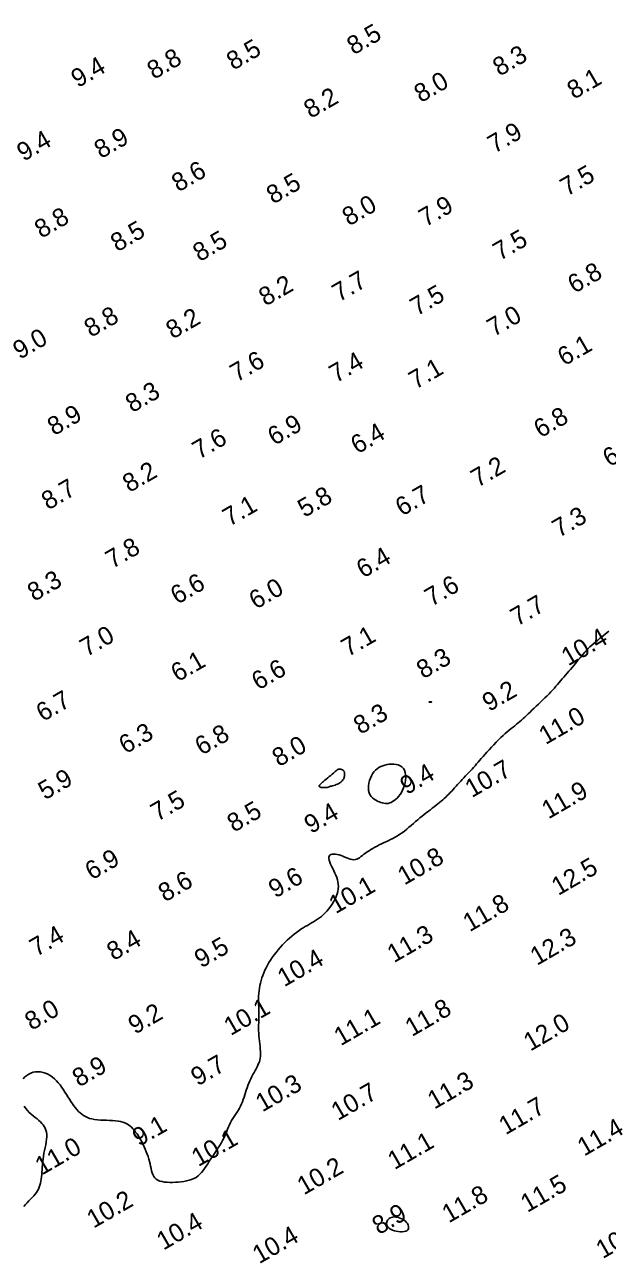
# Model space of a CAD drawing. Extents: x 3024098 to 3056816, y 418252 to 509144.
# Drawn here: x 3034142.8 to 3034302.4, y 418682.1 to 419020.7 of the extents above; entities that cross this region are included whole.
import ezdxf

# ---------------------------------------------------------------- set-up
doc = ezdxf.new("R2010")
doc.units = 0
doc.layers.add('V-CHAN-CONT-EL10', color=7, linetype='Continuous')
doc.layers.add('V-TOPO-SOUN-0911', color=7, linetype='Continuous')

msp = doc.modelspace()

# ---------------------------------------------------------------- linework, layer by layer
at = {"layer": 'V-CHAN-CONT-EL10'}
for points in [[(3034142.44, 418731.86), (3034142.89, 418732.36), (3034143.39, 418732.79), (3034143.95, 418733.15), (3034144.55, 418733.43), (3034145.18, 418733.63), (3034145.83, 418733.75), (3034146.5, 418733.78), (3034147.18, 418733.72), (3034147.85, 418733.59), (3034148.52, 418733.39), (3034149.18, 418733.11), (3034149.81, 418732.76), (3034150.42, 418732.34), (3034150.99, 418731.87), (3034151.53, 418731.33), (3034152.04, 418730.76), (3034152.52, 418730.15), (3034152.98, 418729.51), (3034153.43, 418728.85), (3034153.85, 418728.19), (3034154.27, 418727.53), (3034154.68, 418726.87), (3034155.08, 418726.23), (3034155.49, 418725.61), (3034155.89, 418725.02), (3034156.29, 418724.45), (3034156.71, 418723.9), (3034157.12, 418723.4), (3034157.55, 418722.93), (3034158, 418722.51), (3034158.46, 418722.12), (3034158.95, 418721.78), (3034159.46, 418721.48), (3034160.02, 418721.23), (3034160.62, 418721.01), (3034161.27, 418720.84), (3034161.98, 418720.71), (3034162.75, 418720.61), (3034163.56, 418720.55), (3034164.4, 418720.51), (3034165.25, 418720.48), (3034166.1, 418720.44), (3034166.93, 418720.4), (3034167.72, 418720.35), (3034168.45, 418720.26), (3034169.12, 418720.13), (3034169.72, 418719.97), (3034170.27, 418719.77), (3034170.77, 418719.53), (3034171.23, 418719.25), (3034171.66, 418718.93), (3034172.07, 418718.57), (3034172.46, 418718.17), (3034172.85, 418717.73), (3034173.23, 418717.26), (3034173.61, 418716.75), (3034173.97, 418716.21), (3034174.32, 418715.65), (3034174.66, 418715.06), (3034174.99, 418714.45), (3034175.3, 418713.82), (3034175.6, 418713.18), (3034175.88, 418712.53), (3034176.14, 418711.87), (3034176.39, 418711.2), (3034176.62, 418710.53), (3034176.82, 418709.86), (3034177.01, 418709.2), (3034177.17, 418708.54), (3034177.32, 418707.9), (3034177.46, 418707.28), (3034177.6, 418706.67), (3034177.77, 418706.11), (3034177.96, 418705.59), (3034178.2, 418705.11), (3034178.5, 418704.69), (3034178.88, 418704.34), (3034179.34, 418704.05), (3034179.87, 418703.83), (3034180.48, 418703.67), (3034181.13, 418703.57), (3034181.83, 418703.5), (3034182.57, 418703.48), (3034183.33, 418703.48), (3034184.11, 418703.51), (3034184.89, 418703.56), (3034185.66, 418703.63), (3034186.43, 418703.73), (3034187.17, 418703.86), (3034187.89, 418704.03), (3034188.57, 418704.25), (3034189.21, 418704.52), (3034189.8, 418704.85), (3034190.34, 418705.23), (3034190.83, 418705.68), (3034191.29, 418706.17), (3034191.72, 418706.72), (3034192.13, 418707.3), (3034192.54, 418707.92), (3034192.96, 418708.57), (3034193.39, 418709.24), (3034193.85, 418709.93), (3034194.33, 418710.64), (3034194.82, 418711.36), (3034195.3, 418712.08), (3034195.77, 418712.8), (3034196.22, 418713.52), (3034196.64, 418714.22), (3034197.02, 418714.91), (3034197.36, 418715.58), (3034197.65, 418716.23), (3034197.91, 418716.86), (3034198.16, 418717.48), (3034198.4, 418718.08), (3034198.65, 418718.67), (3034198.9, 418719.26), (3034199.19, 418719.83), (3034199.51, 418720.39), (3034199.85, 418720.95), (3034200.22, 418721.51), (3034200.59, 418722.07), (3034200.96, 418722.63), (3034201.32, 418723.2), (3034201.67, 418723.77), (3034201.98, 418724.36), (3034202.25, 418724.96), (3034202.5, 418725.58), (3034202.72, 418726.2), (3034202.93, 418726.83), (3034203.12, 418727.47), (3034203.32, 418728.11), (3034203.52, 418728.75), (3034203.74, 418729.39), (3034203.98, 418730.03), (3034204.24, 418730.66), (3034204.51, 418731.28), (3034204.79, 418731.88), (3034205.07, 418732.47), (3034205.36, 418733.04), (3034205.65, 418733.59), (3034205.93, 418734.11), (3034206.21, 418734.61), (3034206.47, 418735.09), (3034206.71, 418735.55), (3034206.92, 418736.02), (3034207.11, 418736.49), (3034207.26, 418736.99), (3034207.37, 418737.51), (3034207.44, 418738.07), (3034207.45, 418738.68), (3034207.43, 418739.32), (3034207.37, 418740), (3034207.3, 418740.71), (3034207.21, 418741.43), (3034207.12, 418742.17), (3034207.03, 418742.91), (3034206.97, 418743.65), (3034206.93, 418744.38), (3034206.91, 418745.11), (3034206.91, 418745.83), (3034206.92, 418746.54), (3034206.94, 418747.25), (3034206.95, 418747.97), (3034206.97, 418748.68), (3034206.97, 418749.4), (3034206.97, 418750.13), (3034206.95, 418750.85), (3034206.93, 418751.59), (3034206.91, 418752.32), (3034206.9, 418753.05), (3034206.9, 418753.78), (3034206.92, 418754.51), (3034206.96, 418755.23), (3034207.02, 418755.95), (3034207.12, 418756.66), (3034207.24, 418757.37), (3034207.39, 418758.07), (3034207.57, 418758.77), (3034207.78, 418759.47), (3034208.03, 418760.17), (3034208.3, 418760.87), (3034208.61, 418761.57), (3034208.96, 418762.27), (3034209.33, 418762.98), (3034209.74, 418763.68), (3034210.18, 418764.38), (3034210.65, 418765.08), (3034211.15, 418765.78), (3034211.69, 418766.47), (3034212.25, 418767.17), (3034212.84, 418767.85), (3034213.45, 418768.53), (3034214.08, 418769.18), (3034214.71, 418769.81), (3034215.36, 418770.41), (3034216, 418770.97), (3034216.64, 418771.5), (3034217.27, 418771.97), (3034217.89, 418772.41), (3034218.51, 418772.82), (3034219.11, 418773.2), (3034219.7, 418773.55), (3034220.29, 418773.89), (3034220.86, 418774.22), (3034221.43, 418774.55), (3034221.98, 418774.88), (3034222.53, 418775.22), (3034223.07, 418775.57), (3034223.6, 418775.95), (3034224.12, 418776.36), (3034224.63, 418776.8), (3034225.14, 418777.28), (3034225.64, 418777.82), (3034226.13, 418778.4), (3034226.6, 418779.03), (3034227.05, 418779.69), (3034227.46, 418780.38), (3034227.84, 418781.09), (3034228.16, 418781.79), (3034228.42, 418782.5), (3034228.6, 418783.19), (3034228.71, 418783.86), (3034228.75, 418784.52), (3034228.73, 418785.15), (3034228.64, 418785.77), (3034228.5, 418786.39), (3034228.31, 418787), (3034228.08, 418787.62), (3034227.81, 418788.23), (3034227.51, 418788.86), (3034227.2, 418789.48), (3034226.9, 418790.09), (3034226.62, 418790.67), (3034226.38, 418791.22), (3034226.21, 418791.73), (3034226.1, 418792.18), (3034226.1, 418792.56), (3034226.2, 418792.88), (3034226.4, 418793.12), (3034226.69, 418793.29), (3034227.05, 418793.39), (3034227.47, 418793.43), (3034227.94, 418793.41), (3034228.44, 418793.34), (3034228.95, 418793.21), (3034229.48, 418793.03), (3034230, 418792.82), (3034230.52, 418792.59), (3034231.04, 418792.37), (3034231.54, 418792.17), (3034232.03, 418792), (3034232.5, 418791.89), (3034232.95, 418791.84), (3034233.38, 418791.89), (3034233.78, 418792), (3034234.17, 418792.19), (3034234.56, 418792.42), (3034234.95, 418792.71), (3034235.35, 418793.02), (3034235.76, 418793.35), (3034236.19, 418793.68), (3034236.66, 418794.02), (3034237.15, 418794.35), (3034237.66, 418794.67), (3034238.2, 418794.99), (3034238.76, 418795.31), (3034239.34, 418795.62), (3034239.93, 418795.92), (3034240.53, 418796.22), (3034241.15, 418796.51), (3034241.77, 418796.8), (3034242.4, 418797.09), (3034243.04, 418797.4), (3034243.68, 418797.72), (3034244.31, 418798.06), (3034244.95, 418798.43), (3034245.59, 418798.83), (3034246.22, 418799.27), (3034246.85, 418799.74), (3034247.47, 418800.24), (3034248.09, 418800.75), (3034248.7, 418801.27), (3034249.31, 418801.8), (3034249.92, 418802.33), (3034250.51, 418802.84), (3034251.11, 418803.33), (3034251.7, 418803.81), (3034252.28, 418804.28), (3034252.85, 418804.73), (3034253.41, 418805.16), (3034253.95, 418805.58), (3034254.49, 418805.99), (3034255, 418806.39), (3034255.5, 418806.78), (3034255.98, 418807.16), (3034256.45, 418807.53), (3034256.9, 418807.91), (3034257.34, 418808.28), (3034257.77, 418808.66), (3034258.19, 418809.04), (3034258.6, 418809.43), (3034259, 418809.84), (3034259.4, 418810.26), (3034259.8, 418810.68), (3034260.19, 418811.12), (3034260.59, 418811.56), (3034261, 418812.01), (3034261.41, 418812.47), (3034261.83, 418812.93), (3034262.26, 418813.4), (3034262.71, 418813.88), (3034263.15, 418814.35), (3034263.6, 418814.83), (3034264.05, 418815.3), (3034264.5, 418815.77), (3034264.94, 418816.24), (3034265.37, 418816.71), (3034265.78, 418817.17), (3034266.19, 418817.63), (3034266.6, 418818.1), (3034267.01, 418818.58), (3034267.44, 418819.08), (3034267.89, 418819.6), (3034268.38, 418820.15), (3034268.9, 418820.74), (3034269.46, 418821.36), (3034270.05, 418822.02), (3034270.67, 418822.69), (3034271.31, 418823.37), (3034271.96, 418824.05), (3034272.61, 418824.7), (3034273.25, 418825.33), (3034273.87, 418825.92), (3034274.46, 418826.45), (3034275.03, 418826.94), (3034275.58, 418827.4), (3034276.1, 418827.82), (3034276.61, 418828.22), (3034277.1, 418828.6), (3034277.57, 418828.98), (3034278.03, 418829.35), (3034278.48, 418829.74), (3034278.92, 418830.13), (3034279.37, 418830.54), (3034279.82, 418830.96), (3034280.28, 418831.4), (3034280.76, 418831.86), (3034281.26, 418832.34), (3034281.79, 418832.85), (3034282.35, 418833.38), (3034282.93, 418833.93), (3034283.54, 418834.49), (3034284.15, 418835.07), (3034284.75, 418835.65), (3034285.35, 418836.23), (3034285.93, 418836.79), (3034286.47, 418837.35), (3034286.98, 418837.88), (3034287.46, 418838.4), (3034287.92, 418838.9), (3034288.36, 418839.4), (3034288.78, 418839.9), (3034289.2, 418840.39), (3034289.62, 418840.88), (3034290.05, 418841.39), (3034290.49, 418841.9), (3034290.94, 418842.42), (3034291.4, 418842.96), (3034291.86, 418843.49), (3034292.33, 418844.03), (3034292.79, 418844.57), (3034293.24, 418845.1), (3034293.69, 418845.64), (3034294.12, 418846.16), (3034294.55, 418846.69), (3034294.97, 418847.2), (3034295.4, 418847.71), (3034295.83, 418848.22), (3034296.27, 418848.72), (3034296.72, 418849.21), (3034297.19, 418849.7), (3034297.68, 418850.18), (3034298.19, 418850.66), (3034298.72, 418851.12), (3034299.25, 418851.58), (3034299.79, 418852.03), (3034300.32, 418852.47), (3034300.85, 418852.89), (3034301.37, 418853.3), (3034301.87, 418853.7), (3034302.36, 418854.09), (3034302.83, 418854.46)], [(3034142.61, 418696.84), (3034143.06, 418697.38), (3034143.52, 418697.89), (3034143.98, 418698.38), (3034144.44, 418698.85), (3034144.88, 418699.32), (3034145.3, 418699.77), (3034145.69, 418700.23), (3034146.04, 418700.69), (3034146.35, 418701.16), (3034146.6, 418701.65), (3034146.82, 418702.15), (3034147, 418702.67), (3034147.15, 418703.21), (3034147.27, 418703.77), (3034147.36, 418704.36), (3034147.44, 418704.97), (3034147.5, 418705.6), (3034147.56, 418706.26), (3034147.6, 418706.94), (3034147.66, 418707.64), (3034147.71, 418708.37), (3034147.79, 418709.11), (3034147.88, 418709.87), (3034147.99, 418710.65), (3034148.12, 418711.43), (3034148.28, 418712.23), (3034148.44, 418713.02), (3034148.58, 418713.8), (3034148.71, 418714.55), (3034148.81, 418715.29), (3034148.87, 418715.98), (3034148.86, 418716.63), (3034148.79, 418717.22), (3034148.66, 418717.77), (3034148.46, 418718.28), (3034148.21, 418718.75), (3034147.9, 418719.2), (3034147.55, 418719.63), (3034147.14, 418720.05), (3034146.69, 418720.46), (3034146.21, 418720.87), (3034145.7, 418721.29), (3034145.17, 418721.72), (3034144.63, 418722.18), (3034144.1, 418722.66), (3034143.6, 418723.18), (3034143.12, 418723.73), (3034142.68, 418724.34)]]:
    msp.add_lwpolyline(points, dxfattribs=at)
for points in [[(3034253.66, 418835.03), (3034253.65, 418835.04), (3034253.65, 418835.05), (3034253.65, 418835.06), (3034253.66, 418835.08), (3034253.66, 418835.09), (3034253.67, 418835.1), (3034253.67, 418835.11), (3034253.68, 418835.12), (3034253.68, 418835.13), (3034253.69, 418835.14), (3034253.69, 418835.15), (3034253.7, 418835.15), (3034253.7, 418835.15), (3034253.71, 418835.16), (3034253.71, 418835.16), (3034253.72, 418835.16), (3034253.73, 418835.17), (3034253.74, 418835.17), (3034253.76, 418835.17), (3034253.78, 418835.17), (3034253.81, 418835.17), (3034253.84, 418835.16), (3034253.89, 418835.16), (3034253.95, 418835.16), (3034254.01, 418835.15), (3034254.08, 418835.14), (3034254.14, 418835.13), (3034254.19, 418835.12), (3034254.24, 418835.11), (3034254.27, 418835.1), (3034254.28, 418835.09), (3034254.27, 418835.08), (3034254.24, 418835.07), (3034254.19, 418835.05), (3034254.13, 418835.04), (3034254.07, 418835.03), (3034254, 418835.02), (3034253.93, 418835.02), (3034253.87, 418835.01), (3034253.82, 418835), (3034253.78, 418835), (3034253.74, 418835), (3034253.72, 418835), (3034253.69, 418835), (3034253.68, 418835), (3034253.67, 418835.01), (3034253.66, 418835.02)], [(3034237.05, 418810.83), (3034237, 418811.47), (3034237.03, 418812.15), (3034237.13, 418812.84), (3034237.3, 418813.54), (3034237.53, 418814.21), (3034237.81, 418814.85), (3034238.14, 418815.43), (3034238.51, 418815.95), (3034238.92, 418816.4), (3034239.36, 418816.79), (3034239.84, 418817.12), (3034240.36, 418817.39), (3034240.9, 418817.62), (3034241.48, 418817.79), (3034242.08, 418817.93), (3034242.71, 418818.02), (3034243.35, 418818.07), (3034243.98, 418818.05), (3034244.6, 418817.98), (3034245.18, 418817.84), (3034245.71, 418817.61), (3034246.18, 418817.3), (3034246.56, 418816.9), (3034246.85, 418816.39), (3034247.05, 418815.8), (3034247.16, 418815.14), (3034247.2, 418814.44), (3034247.15, 418813.71), (3034247.04, 418812.97), (3034246.87, 418812.24), (3034246.64, 418811.54), (3034246.35, 418810.89), (3034246.02, 418810.28), (3034245.66, 418809.73), (3034245.27, 418809.23), (3034244.86, 418808.78), (3034244.44, 418808.39), (3034244.02, 418808.06), (3034243.61, 418807.79), (3034243.21, 418807.58), (3034242.82, 418807.42), (3034242.43, 418807.32), (3034242.05, 418807.28), (3034241.65, 418807.28), (3034241.25, 418807.33), (3034240.83, 418807.42), (3034240.39, 418807.55), (3034239.93, 418807.71), (3034239.45, 418807.92), (3034238.98, 418808.17), (3034238.52, 418808.47), (3034238.1, 418808.83), (3034237.73, 418809.23), (3034237.42, 418809.7), (3034237.19, 418810.23)], [(3034223.62, 418812.3), (3034223.64, 418812.34), (3034223.68, 418812.39), (3034223.75, 418812.47), (3034223.84, 418812.57), (3034223.98, 418812.7), (3034224.16, 418812.87), (3034224.4, 418813.08), (3034224.71, 418813.34), (3034225.06, 418813.64), (3034225.44, 418813.97), (3034225.85, 418814.31), (3034226.26, 418814.65), (3034226.66, 418814.99), (3034227.04, 418815.31), (3034227.38, 418815.6), (3034227.67, 418815.86), (3034227.91, 418816.07), (3034228.11, 418816.25), (3034228.29, 418816.39), (3034228.44, 418816.51), (3034228.57, 418816.59), (3034228.71, 418816.65), (3034228.84, 418816.69), (3034228.98, 418816.71), (3034229.12, 418816.71), (3034229.27, 418816.7), (3034229.42, 418816.67), (3034229.57, 418816.63), (3034229.71, 418816.59), (3034229.83, 418816.53), (3034229.95, 418816.47), (3034230.04, 418816.41), (3034230.12, 418816.34), (3034230.19, 418816.27), (3034230.25, 418816.19), (3034230.29, 418816.11), (3034230.33, 418816.02), (3034230.37, 418815.92), (3034230.39, 418815.82), (3034230.42, 418815.7), (3034230.44, 418815.58), (3034230.45, 418815.45), (3034230.46, 418815.3), (3034230.45, 418815.15), (3034230.44, 418814.98), (3034230.41, 418814.8), (3034230.36, 418814.6), (3034230.3, 418814.39), (3034230.22, 418814.17), (3034230.12, 418813.95), (3034229.99, 418813.73), (3034229.83, 418813.5), (3034229.64, 418813.29), (3034229.42, 418813.09), (3034229.15, 418812.9), (3034228.85, 418812.73), (3034228.53, 418812.58), (3034228.18, 418812.45), (3034227.84, 418812.34), (3034227.5, 418812.24), (3034227.17, 418812.15), (3034226.88, 418812.07), (3034226.64, 418812), (3034226.44, 418811.93), (3034226.29, 418811.88), (3034226.16, 418811.82), (3034226.06, 418811.78), (3034225.97, 418811.74), (3034225.88, 418811.71), (3034225.77, 418811.68), (3034225.64, 418811.66), (3034225.47, 418811.64), (3034225.28, 418811.63), (3034225.07, 418811.62), (3034224.85, 418811.62), (3034224.62, 418811.63), (3034224.41, 418811.64), (3034224.21, 418811.66), (3034224.03, 418811.69), (3034223.88, 418811.72), (3034223.77, 418811.76), (3034223.68, 418811.8), (3034223.61, 418811.85), (3034223.56, 418811.9), (3034223.53, 418811.95), (3034223.51, 418811.99), (3034223.5, 418812.03), (3034223.5, 418812.07), (3034223.51, 418812.1), (3034223.52, 418812.13), (3034223.53, 418812.16), (3034223.54, 418812.19), (3034223.56, 418812.21), (3034223.58, 418812.24), (3034223.6, 418812.27)], [(3034247.79, 418690.46), (3034247.94, 418690.74), (3034248, 418691.07), (3034247.97, 418691.42), (3034247.86, 418691.79), (3034247.67, 418692.16), (3034247.42, 418692.51), (3034247.11, 418692.85), (3034246.74, 418693.14), (3034246.33, 418693.4), (3034245.89, 418693.61), (3034245.43, 418693.78), (3034244.97, 418693.9), (3034244.51, 418693.97), (3034244.06, 418693.99), (3034243.65, 418693.95), (3034243.28, 418693.87), (3034242.95, 418693.73), (3034242.67, 418693.55), (3034242.43, 418693.34), (3034242.24, 418693.1), (3034242.1, 418692.85), (3034242, 418692.58), (3034241.96, 418692.3), (3034241.96, 418692.02), (3034242.02, 418691.75), (3034242.14, 418691.49), (3034242.31, 418691.24), (3034242.54, 418690.99), (3034242.84, 418690.77), (3034243.19, 418690.56), (3034243.61, 418690.38), (3034244.1, 418690.22), (3034244.63, 418690.09), (3034245.18, 418689.99), (3034245.73, 418689.93), (3034246.27, 418689.93), (3034246.76, 418689.97), (3034247.2, 418690.07), (3034247.54, 418690.23)]]:
    msp.add_lwpolyline(points, close=True, dxfattribs=at)

# ---------------------------------------------------------------- texts
at = {"layer": 'V-TOPO-SOUN-0911'}
for s, p in [('8.5', (3034232.95, 419012.25)), ('8.5', (3034199.98, 419008.05)), ('8.8', (3034178.23, 419005.53)), ('8.3', (3034272.89, 419006.41)), ('9.4', (3034157.4, 419003.26)), ('8.0', (3034251.35, 418999.16)), ('8.1', (3034293.27, 419000.09)), ('8.2', (3034221.15, 418994.83)), ('7.9', (3034271.51, 418985.28)), ('9.4', (3034142.54, 418983.08)), ('8.9', (3034163.73, 418983.81)), ('8.6', (3034184.93, 418974.69)), ('8.5', (3034210.9, 418971.37)), ('7.5', (3034291.38, 418973.54)), ('8.0', (3034231.66, 418965.37)), ('7.9', (3034252.64, 418965.14)), ('8.8', (3034147.39, 418961.99)), ('8.5', (3034168.22, 418958.28)), ('8.5', (3034190.76, 418955.59)), ('7.5', (3034272.97, 418955.89)), ('7.7', (3034228.92, 418944.57)), ('6.8', (3034293.42, 418946.9)), ('8.2', (3034208.81, 418943.42)), ('7.5', (3034250.27, 418940.73)), ('8.8', (3034160.98, 418934.86)), ('8.2', (3034183.38, 418934.4)), ('7.0', (3034271.33, 418935.05)), ('9.0', (3034141.47, 418928.82)), ('6.1', (3034290.65, 418927.03)), ('7.6', (3034200.94, 418922.62)), ('7.4', (3034228.1, 418922.39)), ('7.1', (3034249.9, 418920.63)), ('8.3', (3034172.3, 418914.22)), ('8.9', (3034150.9, 418907.92)), ('6.8', (3034284.14, 418907.3)), ('6.9', (3034211.24, 418905.23)), ('7.6', (3034190.6, 418901.46)), ('6.4', (3034233.98, 418902.9)), ('6.6', (3034303, 418899.36)), ('7.2', (3034266.91, 418893.75)), ('8.2', (3034171.51, 418892.34)), ('8.7', (3034149.26, 418887.55)), ('5.8', (3034219.47, 418885.51)), ('6.7', (3034246.21, 418885.87)), ('7.1', (3034198.92, 418883.07)), ('7.3', (3034289.19, 418880)), ('7.8', (3034166.82, 418871.5)), ('6.4', (3034235.55, 418868.88)), ('8.3', (3034145.43, 418862.51)), ('6.6', (3034184.63, 418861.7)), ('6.0', (3034206.14, 418860.35)), ('7.6', (3034254.25, 418861.14)), ('7.7', (3034277.74, 418855.72)), ('7.0', (3034159.81, 418847.35)), ('7.1', (3034231.4, 418847.34)), ('10.4 ', (3034291.69, 418844.82)), ('6.1', (3034184.74, 418840.45)), ('8.3', (3034252.02, 418841.29)), ('6.6', (3034206.84, 418838.18)), ('9.2', (3034270.03, 418832.33)), ('6.7', (3034147.82, 418829.57)), ('8.3', (3034234.76, 418826.06)), ('11.0 ', (3034285.53, 418823.27)), ('6.3', (3034170.49, 418820.72)), ('6.8', (3034191.32, 418820.35)), ('8.0', (3034212.47, 418817.2)), ('9.4', (3034247.52, 418809.56)), ('10.7 ', (3034265.31, 418808.73)), ('5.9', (3034148.38, 418808.12)), ('7.5', (3034179.18, 418802.24)), ('11.9 ', (3034286.31, 418802.89)), ('8.5', (3034200.14, 418799.26)), ('9.4', (3034221.25, 418798.87)), ('6.9', (3034161.21, 418786.17)), ('10.8 ', (3034246.84, 418784.78)), ('9.6', (3034211.47, 418781.22)), ('12.5 ', (3034288.99, 418781.93)), ('8.6', (3034181.28, 418780.17)), ('10.1 ', (3034228.02, 418776.92)), ('11.8 ', (3034264.72, 418771.99)), ('7.4', (3034146.05, 418765.2)), ('11.3 ', (3034243.98, 418763.49)), ('12.3 ', (3034283.16, 418762.77)), ('8.4', (3034167.18, 418764.09)), ('9.5', (3034191.18, 418762.05)), ('10.4 ', (3034213.93, 418756.9)), ('8.0', (3034144.72, 418744.96)), ('10.1 ', (3034199.25, 418743.53)), ('11.8 ', (3034248.9, 418743.28)), ('9.2', (3034173.05, 418743.91)), ('11.1 ', (3034229.4, 418740.74)), ('12.0 ', (3034281.34, 418739.28)), ('8.9', (3034157.73, 418729.44)), ('9.7', (3034190.21, 418729.74)), ('10.3 ', (3034207.93, 418722.61)), ('11.3 ', (3034255.04, 418723.37)), ('10.7 ', (3034228.63, 418720.25)), ('11.7 ', (3034274.56, 418716.35)), ('9.1', (3034174.18, 418713.18)), ('11.4 ', (3034296.08, 418710.51)), ('11.0 ', (3034147.54, 418705.32)), ('10.1 ', (3034190.39, 418707.63)), ('11.1 ', (3034244.13, 418706.81)), ('10.2 ', (3034219.31, 418699.88)), ('11.5 ', (3034280.52, 418695.09)), ('11.8 ', (3034258.98, 418692.2)), ('10.2 ', (3034161.7, 418690.76)), ('10.4 ', (3034180.83, 418684.75)), ('8.9', (3034239.85, 418688.99)), ('10.2 ', (3034301.17, 418682.42)), ('10.4 ', (3034207.07, 418681.01))]:
    msp.add_text(s, height=5, rotation=30, dxfattribs=at).set_placement(p)

doc.saveas('drawing.dxf')
